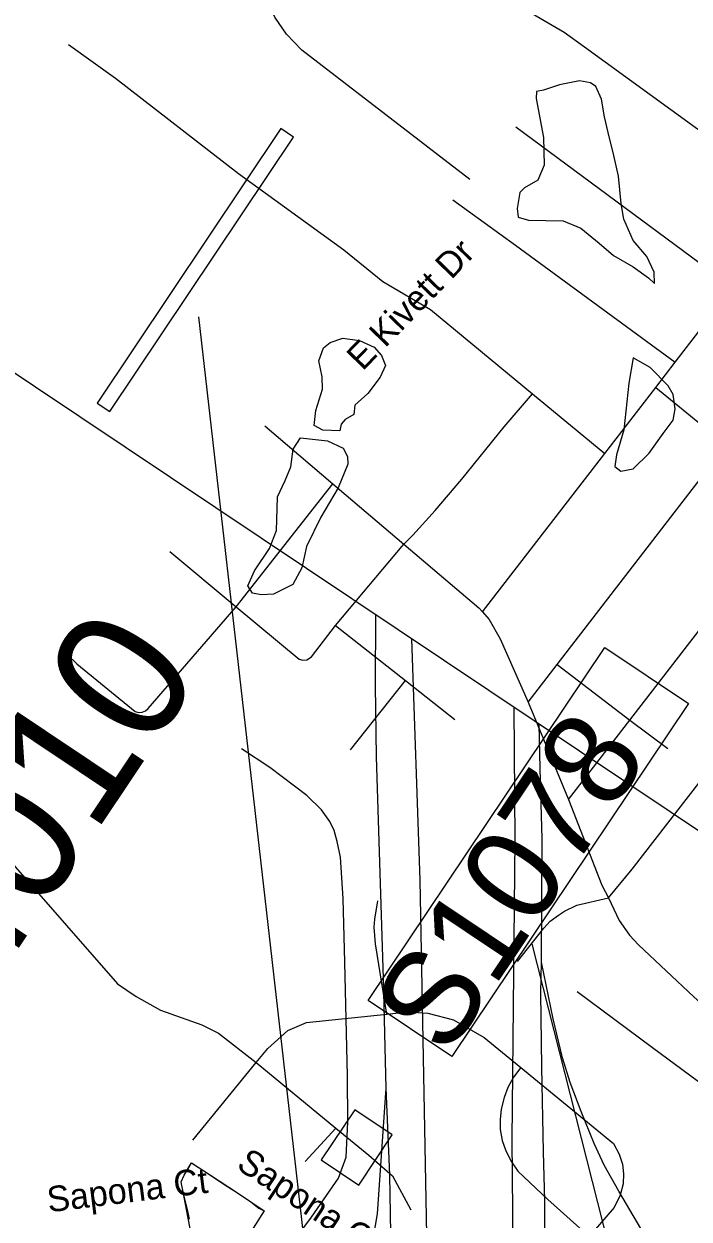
# Model space of a CAD drawing. Extents: x 1716282 to 1717158, y 799307 to 801078.
# Drawn here: x 1716814.2 to 1716850, y 800859.9 to 800924.3 of the extents above; entities that cross this region are included whole.
import ezdxf

# ---------------------------------------------------------------- set-up
doc = ezdxf.new("R2010")
doc.units = 0
for name, color, linetype in [('Exist Hydrographic Misc Water Feature', 7, 'Continuous'), ('Exist Hydrographic Pond Under 1500 Sq Ft', 7, 'Continuous'), ('Exist Road Non-System Type 51', 7, 'Continuous'), ('Exist Road Non-System Type 51 Label', 7, 'Continuous'), ('Exist Road Primary Interstate Divided Center Attributed', 7, 'Continuous'), ('Exist Road Primary US Structure Ovrhead Sign CELL', 7, 'Continuous'), ('Exist Road Primary US Structure Standard Bridge Number Label', 7, 'Continuous'), ('Exist Road Secondary Type 51 Attributed', 7, 'Continuous'), ('Exist Road Secondary Type 51 Label', 7, 'Continuous'), ('Old_Level_1', 7, 'Continuous'), ('Prop DSN Text', 7, 'Continuous'), ('Prop Road Primary US Projected', 7, 'Continuous')]:
    doc.layers.add(name, color=color, linetype=linetype)

msp = doc.modelspace()

# ---------------------------------------------------------------- linework, layer by layer
at = {"layer": 'Exist Hydrographic Misc Water Feature'}
for points in [[(1716830.219, 800863.057), (1716832.246, 800861.705), (1716834.055, 800864.405), (1716832.028, 800865.756), (1716830.219, 800863.057)], [(1716830.219, 800863.057), (1716832.246, 800861.705), (1716834.055, 800864.405), (1716832.028, 800865.756), (1716830.219, 800863.057)], [(1716823.118, 800859.861), (1716823.019, 800860.386), (1716822.827, 800861.185), (1716822.742, 800861.525), (1716822.712, 800861.686), (1716822.675, 800861.888), (1716822.839, 800862.231), (1716823.093, 800862.654), (1716823.233, 800862.91)], [(1716823.233, 800862.91), (1716824.255, 800862.247), (1716825.709, 800861.29), (1716826.428, 800860.798), (1716827.147, 800860.308), (1716826.681, 800859.574), (1716824.599, 800856.321), (1716824.327, 800856.437), (1716823.975, 800856.643), (1716823.711, 800856.822), (1716823.54, 800857.395), (1716822.742, 800861.525), (1716822.712, 800861.686), (1716822.675, 800861.888), (1716822.839, 800862.231), (1716823.233, 800862.91)], [(1716823.233, 800862.91), (1716824.255, 800862.247), (1716825.022, 800861.723), (1716825.709, 800861.29), (1716826.428, 800860.798), (1716826.866, 800860.464), (1716827.147, 800860.308), (1716826.681, 800859.574)]]:
    msp.add_lwpolyline(points, dxfattribs=at)
at = {"layer": 'Exist Hydrographic Pond Under 1500 Sq Ft'}
for points in [[(1716843.057, 800920.998), (1716842.207, 800920.716), (1716841.825, 800920.64), (1716841.814, 800920.27), (1716842.201, 800918.168), (1716842.242, 800916.676), (1716841.892, 800915.87), (1716841.183, 800915.447), (1716840.921, 800915.197), (1716840.778, 800914.347), (1716840.842, 800913.879), (1716841.386, 800913.704), (1716843.259, 800913.679), (1716844.217, 800913.274), (1716845.195, 800912.478), (1716845.978, 800911.812), (1716847.033, 800911.201), (1716847.859, 800910.6), (1716848.174, 800910.295), (1716848.164, 800910.916), (1716847.774, 800911.744), (1716847.035, 800912.616), (1716846.526, 800913.761), (1716846.386, 800914.611), (1716846.237, 800916.081), (1716845.989, 800917.192), (1716845.686, 800918.434), (1716845.492, 800919.273), (1716845.331, 800920.232), (1716845.027, 800920.908), (1716844.734, 800921.104), (1716844.146, 800921.214), (1716843.057, 800920.998)], [(1716831.226, 800902.357), (1716830.317, 800902.385), (1716829.849, 800902.64), (1716829.931, 800903.456), (1716830.295, 800904.605), (1716830.269, 800905.26), (1716830.097, 800906.13), (1716830.339, 800906.838), (1716830.701, 800907.118), (1716831.383, 800907.358), (1716832.278, 800907.223), (1716833.08, 800906.86), (1716833.48, 800906.418), (1716833.693, 800905.87), (1716833.397, 800905.255), (1716832.741, 800904.36), (1716832.031, 800903.733), (1716831.99, 800903.238), (1716831.521, 800902.972), (1716831.293, 800902.718), (1716831.226, 800902.357)], [(1716848.91, 800904.79), (1716847.953, 800905.774), (1716847.029, 800906.294), (1716846.801, 800904.929), (1716846.536, 800902.413), (1716846.127, 800901.071), (1716846.047, 800900.44), (1716846.362, 800900.18), (1716847.039, 800900.314), (1716847.898, 800901.159), (1716848.656, 800902.218), (1716849.188, 800902.939), (1716849.302, 800903.549), (1716849.18, 800904.316), (1716848.91, 800904.79)], [(1716829.113, 800901.973), (1716830.57, 800901.81), (1716831.411, 800901.421), (1716831.637, 800900.979), (1716831.65, 800900.565), (1716831.139, 800899.282), (1716830.2, 800897.706), (1716829.435, 800896.129), (1716829.179, 800894.966), (1716828.695, 800894.071), (1716827.652, 800893.551), (1716826.996, 800893.526), (1716826.529, 800893.607), (1716826.276, 800894.008), (1716826.638, 800894.81), (1716827.443, 800896.012), (1716827.806, 800896.987), (1716827.848, 800898.177), (1716827.863, 800898.806), (1716828.279, 800899.688), (1716828.588, 800900.409), (1716828.71, 800901.372), (1716829.113, 800901.973)]]:
    msp.add_lwpolyline(points, dxfattribs=at)
at = {"layer": 'Exist Road Non-System Type 51'}
for p, q in [((1716844.419, 800923.047), (1716855.928, 800914.679)), ((1716849.299, 800906.055), (1716852.603, 800910.361)), ((1716848.25, 800904.697), (1716849.299, 800906.055)), ((1716845.507, 800901.134), (1716848.25, 800904.697)), ((1716841.615, 800904.343), (1716845.507, 800901.134)), ((1716827.18, 800902.62), (1716830.844, 800899.494)), ((1716842.943, 800889.756), (1716852.085, 800901.635)), ((1716838.908, 800892.609), (1716845.507, 800901.134)), ((1716825.641, 800892.874), (1716830.844, 800899.494)), ((1716830.844, 800899.494), (1716834.68, 800896.242)), ((1716846.846, 800886.755), (1716856.006, 800898.627)), ((1716831, 800891.865), (1716834.68, 800896.242)), ((1716822.065, 800895.858), (1716825.641, 800892.874)), ((1716831, 800891.865), (1716834.771, 800888.898)), ((1716841.381, 800887.739), (1716842.943, 800889.756)), ((1716842.943, 800889.756), (1716846.846, 800886.755)), ((1716831.806, 800885.166), (1716834.771, 800888.898)), ((1716834.771, 800888.898), (1716837.431, 800886.797)), ((1716841.381, 800887.739), (1716843.54, 800882.493)), ((1716843.54, 800882.493), (1716846.846, 800886.755)), ((1716846.846, 800886.755), (1716848.892, 800885.235)), ((1716823.308, 800864.128), (1716826.711, 800868.304)), ((1716826.711, 800868.304), (1716831.009, 800864.777)), ((1716829.357, 800862.971), (1716831.009, 800864.777))]:
    msp.add_line(p, q, dxfattribs=at)
for points in [[(1716838.24, 800915.894), (1716829.182, 800922.872), (1716828.358, 800923.736), (1716827.733, 800924.647), (1716827.302, 800925.524), (1716827.178, 800925.912), (1716827.134, 800926.217), (1716827.145, 800926.521), (1716827.265, 800927.013), (1716827.511, 800927.457), (1716829.855, 800930.393), (1716830.26, 800930.737), (1716830.675, 800930.905), (1716831.117, 800930.951), (1716831.664, 800930.836), (1716836.977, 800927.554), (1716843.311, 800923.852), (1716844.419, 800923.047)], [(1716816.602, 800923.181), (1716819.138, 800921.366), (1716825.765, 800916.235), (1716831.438, 800912.117), (1716833.537, 800910.413)], [(1716840.706, 800918.744), (1716851.07, 800911.075), (1716851.635, 800910.729), (1716852.603, 800910.361)], [(1716837.313, 800914.802), (1716840.696, 800912.372), (1716849.299, 800906.055)], [(1716833.537, 800910.413), (1716836.108, 800908.904), (1716841.615, 800904.343)], [(1716848.25, 800904.697), (1716850.513, 800902.839), (1716852.085, 800901.635)], [(1716834.68, 800896.242), (1716835.165, 800896.726), (1716836.355, 800898.06), (1716837.805, 800899.76), (1716840.085, 800902.565), (1716841.615, 800904.343)], [(1716834.68, 800896.242), (1716838.72, 800892.809), (1716838.908, 800892.609)], [(1716816.556, 800890.292), (1716817.063, 800889.795), (1716820.203, 800887.236), (1716820.382, 800887.181), (1716820.576, 800887.189), (1716820.751, 800887.259), (1716820.902, 800887.383), (1716825.641, 800892.874)], [(1716825.641, 800892.874), (1716829.041, 800890.053), (1716829.235, 800889.993), (1716829.454, 800890.012), (1716829.702, 800890.18), (1716831, 800891.865)], [(1716838.908, 800892.609), (1716839.278, 800892.191), (1716839.874, 800891.151), (1716841.381, 800887.739)], [(1716845.695, 800877.181), (1716846.97, 800878.731), (1716851.257, 800884.239), (1716853.974, 800887.838), (1716855.392, 800889.63)], [(1716809.716, 800883.781), (1716813.743, 800878.848), (1716819.251, 800872.547), (1716820.26, 800871.871), (1716821.573, 800871.13), (1716823.786, 800870.336), (1716824.694, 800869.9), (1716826.711, 800868.304)], [(1716843.54, 800882.493), (1716845.352, 800877.873), (1716845.695, 800877.181)], [(1716833.754, 800870.916), (1716833.143, 800874.71), (1716833.072, 800875.61), (1716833.107, 800876.041), (1716833.266, 800877.023)], [(1716840.798, 800873.758), (1716842.223, 800875.544), (1716842.562, 800875.921), (1716843.014, 800876.26), (1716843.333, 800876.476), (1716844, 800876.795), (1716845.695, 800877.181)], [(1716845.695, 800877.181), (1716846.271, 800875.962), (1716846.841, 800875.177), (1716847.328, 800874.655), (1716850.309, 800871.848), (1716853.851, 800868.675), (1716854.837, 800867.959)], [(1716826.711, 800868.304), (1716827.341, 800869.065), (1716828.432, 800870.033), (1716829.432, 800870.467), (1716833.754, 800870.916)], [(1716833.754, 800870.916), (1716834.888, 800871.038), (1716835.974, 800870.97), (1716837.35, 800870.603), (1716839.001, 800869.664), (1716840.974, 800868.035)], [(1716840.974, 800868.035), (1716840.586, 800867.521), (1716840.278, 800866.959), (1716840.076, 800866.425), (1716839.917, 800865.803), (1716839.861, 800865.241), (1716839.873, 800864.692), (1716839.976, 800864.115), (1716840.168, 800863.552), (1716840.468, 800862.952), (1716840.826, 800862.447), (1716842.433, 800860.936), (1716844.665, 800858.939)], [(1716840.974, 800868.035), (1716845.966, 800863.948), (1716846.281, 800863.367), (1716846.454, 800862.83), (1716846.515, 800862.307), (1716846.49, 800861.77), (1716846.34, 800861.162), (1716846.004, 800860.497), (1716844.665, 800858.939)], [(1716831.009, 800864.777), (1716832.794, 800863.312), (1716834.073, 800862.196), (1716835.044, 800860.377)]]:
    msp.add_lwpolyline(points, dxfattribs=at)
at = {"layer": 'Exist Road Primary Interstate Divided Center Attributed'}
for points in [[(1716835.088, 800891.145), (1716835.541, 800878.131), (1716835.978, 800854.231), (1716836.687, 800821.294), (1716837.624, 800792.348), (1716838.004, 800777.763)], [(1716841.689, 800787.175), (1716841.484, 800799.653), (1716840.807, 800814.818), (1716840.802, 800831.22), (1716840.65, 800839.538), (1716840.717, 800842.78), (1716840.511, 800864.16), (1716840.671, 800880.306), (1716840.628, 800887.437)]]:
    msp.add_lwpolyline(points, dxfattribs=at)
at = {"layer": 'Exist Road Primary US Structure Ovrhead Sign CELL'}
msp.add_line((1716852.51, 800831.62), (1716841.591, 800874.712), dxfattribs=at)
msp.add_lwpolyline([(1716832.759, 800871.647), (1716845.502, 800890.686), (1716850.01, 800887.668), (1716837.267, 800868.629)], close=True, dxfattribs=at)
at = {"layer": 'Exist Road Primary US Structure Standard Bridge Number Label'}
for p, q in [((1716828.048, 800918.648), (1716818.146, 800903.854)), ((1716830.747, 800846.028), (1716823.628, 800908.497))]:
    msp.add_line(p, q, dxfattribs=at)
msp.add_lwpolyline([(1716818.146, 800903.854), (1716818.838, 800903.391), (1716828.739, 800918.185), (1716828.048, 800918.648)], dxfattribs=at)
at = {"layer": 'Exist Road Secondary Type 51 Attributed'}
for points in [[(1716825.733, 800854.617), (1716829.709, 800859.979), (1716831.153, 800862.078), (1716831.567, 800863.213), (1716831.666, 800865.093), (1716831.633, 800867.593), (1716831.491, 800873.713), (1716831.399, 800877.159), (1716831.271, 800879.377), (1716831.088, 800880.219), (1716830.919, 800880.811), (1716830.697, 800881.307), (1716830.237, 800881.935), (1716829.446, 800882.704), (1716827.449, 800884.21), (1716825.921, 800885.223)], [(1716866.929, 800856.114), (1716860.795, 800860.069), (1716855.715, 800863.469), (1716848.078, 800869.106), (1716844.019, 800872.124)]]:
    msp.add_lwpolyline(points, dxfattribs=at)
at = {"layer": 'Prop DSN Text'}
msp.add_lwpolyline([(1716644.267, 800417.02), (1716922.463, 800832.664), (1716560.178, 801075.146), (1716281.982, 800659.503)], close=True, dxfattribs=at)
at = {"layer": 'Prop Road Primary US Projected'}
for points in [[(1716833.72, 800866.937), (1716833.584, 800872.845), (1716833.208, 800884.787), (1716833.147, 800888.637), (1716833.165, 800892.432)], [(1716842.093, 800873.711), (1716842.128, 800880.365), (1716842.013, 800884.163), (1716841.961, 800886.545)], [(1716842.604, 800838.776), (1716842.457, 800842.135), (1716842.509, 800843.769), (1716842.33, 800849.839), (1716842.329, 800851.392), (1716842.31, 800854.694), (1716842.267, 800860.849), (1716842.2, 800863.488), (1716842.116, 800868.054), (1716842.062, 800872.07), (1716842.093, 800873.711)], [(1716847.862, 800858.655), (1716846.267, 800861.383), (1716845.473, 800862.779), (1716844.924, 800863.943), (1716844.223, 800865.675), (1716843.636, 800867.231), (1716843.232, 800868.564), (1716842.716, 800870.67), (1716842.093, 800873.711)], [(1716810.2, 800834.484), (1716813.012, 800835.161), (1716815.408, 800835.967), (1716817.214, 800836.715), (1716819.171, 800837.915), (1716820.456, 800838.56), (1716823.368, 800840.868), (1716825.149, 800842.337), (1716827.137, 800844.644), (1716828.756, 800846.931), (1716830.273, 800849.463), (1716831.752, 800852.732), (1716832.514, 800855.858), (1716833.258, 800860.15), (1716833.72, 800866.937)], [(1716834.544, 800836.759), (1716834.334, 800844.144), (1716834.353, 800846.313), (1716834.166, 800850.802), (1716834.09, 800854.434), (1716833.999, 800858.044), (1716833.925, 800862.262), (1716833.72, 800866.937)]]:
    msp.add_lwpolyline(points, dxfattribs=at)

# ---------------------------------------------------------------- texts
at = {"layer": 'Exist Road Non-System Type 51 Label'}
for rotation, p in [(326.30074, (1716825.592, 800862.633)), (7.04168, (1716815.538, 800860.232))]:
    msp.add_text('Sapona Ct', height=1.3775, rotation=rotation, dxfattribs=at).set_placement(p)
at = {"layer": 'Exist Road Primary US Structure Ovrhead Sign CELL'}
msp.add_text('S1078', height=5.075, rotation=56.20506, dxfattribs=at).set_placement((1716836.998, 800868.529))
at = {"layer": 'Exist Road Secondary Type 51 Label'}
msp.add_text('E Kivett Dr', height=1.3775, rotation=45.8944, dxfattribs=at).set_placement((1716832.457, 800905.547))
at = {"layer": 'Old_Level_1'}
msp.add_text('4010', height=7.128, rotation=56.20506, dxfattribs=at).set_placement((1716812.092, 800871.742))

doc.saveas('drawing.dxf')
